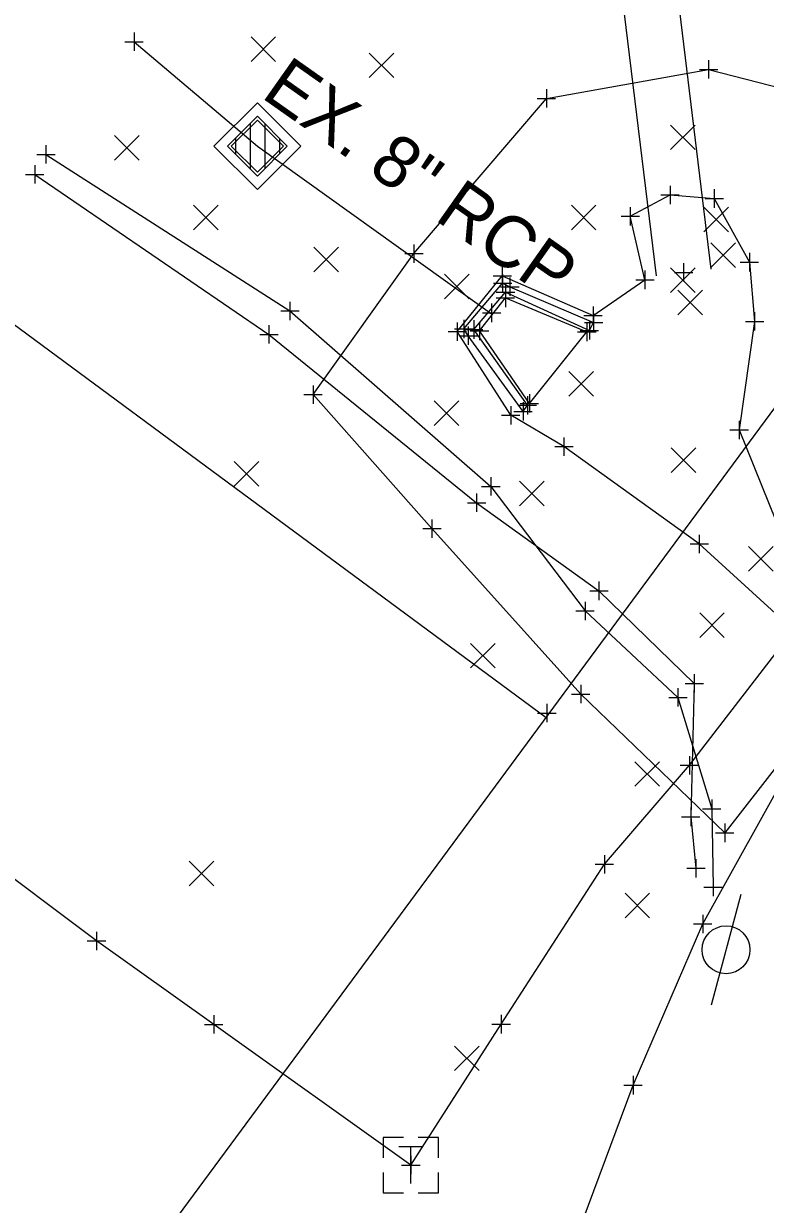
# Model space of a CAD drawing. Extents: x 1324089 to 1329959, y 459099 to 462017.
# Drawn here: x 1325717.7 to 1325758, y 460930.3 to 460994.4 of the extents above; entities that cross this region are included whole.
import ezdxf

# ---------------------------------------------------------------- set-up
doc = ezdxf.new("R2010")
doc.units = 0
for name, color, linetype in [('Default', 7, 'Continuous'), ('DR_X_Cells', 7, 'Continuous'), ('DR_X_Elev_Flow', 7, 'Continuous'), ('DR_X_Storm_Sewer', 7, 'Continuous'), ('DV_X_Property_Line', 7, 'Continuous'), ('GK_Drainage_Nodes', 7, 'Continuous'), ('PV_X_EOP', 7, 'Continuous'), ('RD_X_Wall', 7, 'Continuous'), ('RW_X_Fee_RW', 7, 'Continuous'), ('SV_X_Break_Lines', 7, 'Continuous'), ('SV_X_Random_Point', 7, 'Continuous'), ('SV_X_Shot_Marker', 7, 'Continuous'), ('UT_X_Electric', 7, 'Continuous'), ('UT_X_Telecom', 7, 'Continuous'), ('UT_X_Telecom_Cells', 7, 'Continuous'), ('UT_X_Unknown_Cells', 7, 'Continuous')]:
    doc.layers.add(name, color=color, linetype=linetype)

msp = doc.modelspace()

# ---------------------------------------------------------------- linework, layer by layer
at = {"layer": 'DR_X_Cells'}
for p, q in [((1325730.027, 460986.552), (1325730.027, 460989.039)), ((1325730.827, 460986.598), (1325730.827, 460988.992)), ((1325729.227, 460987.352), (1325729.227, 460988.239)), ((1325731.627, 460987.398), (1325731.627, 460988.192))]:
    msp.add_line(p, q, dxfattribs=at)
for points in [[(1325728.047, 460987.795), (1325730.404, 460990.152), (1325732.761, 460987.795), (1325730.404, 460985.438)], [(1325728.783, 460987.795), (1325730.404, 460989.416), (1325732.024, 460987.795), (1325730.404, 460986.175)], [(1325728.989, 460987.795), (1325730.404, 460989.21), (1325731.818, 460987.795), (1325730.404, 460986.381)]]:
    msp.add_lwpolyline(points, close=True, dxfattribs=at)
at = {"layer": 'DR_X_Elev_Flow'}
for p, q in [((1325723.706, 460993.967), (1325723.706, 460992.967)), ((1325723.206, 460993.467), (1325724.206, 460993.467)), ((1325723.706, 460993.467), (1325723.706, 460993.467)), ((1325753.054, 460980.942), (1325754.054, 460980.942)), ((1325753.554, 460981.442), (1325753.554, 460980.442)), ((1325753.554, 460980.942), (1325753.554, 460980.942))]:
    msp.add_line(p, q, dxfattribs=at)
at = {"layer": 'DR_X_Storm_Sewer'}
for p, q in [((1325747.138, 461045.572), (1325755.043, 460981.125)), ((1325744.161, 461045.207), (1325752.065, 460980.759)), ((1325744.161, 461045.207), (1325752.065, 460980.759)), ((1325723.706, 460993.467), (1325730.404, 460987.795)), ((1325730.404, 460987.795), (1325743.172, 460978.659))]:
    msp.add_line(p, q, dxfattribs=at)
at = {"layer": 'DV_X_Property_Line'}
msp.add_line((1325585.214, 461075.604), (1325746.083, 460956.772), dxfattribs=at)
at = {"layer": 'GK_Drainage_Nodes'}
for p, q in [((1325729.225, 460988.974), (1325729.225, 460988.974)), ((1325729.697, 460988.502), (1325729.697, 460988.502)), ((1325731.111, 460988.502), (1325731.111, 460988.502)), ((1325730.404, 460987.795), (1325730.404, 460987.795)), ((1325730.404, 460987.795), (1325730.404, 460987.795)), ((1325730.404, 460987.795), (1325730.404, 460987.795)), ((1325729.697, 460987.088), (1325729.697, 460987.088)), ((1325731.111, 460987.088), (1325731.111, 460987.088)), ((1325731.582, 460986.617), (1325731.582, 460986.617))]:
    msp.add_line(p, q, dxfattribs=at)
at = {"layer": 'PV_X_EOP'}
msp.add_lwpolyline([(1325745.179, 460973.829), (1325748.299, 460977.713)], dxfattribs=at)
at = {"layer": 'RD_X_Wall'}
for points in [[(1325744.833, 460973.4), (1325741.863, 460977.504), (1325741.618, 460977.871), (1325743.727, 460980.352), (1325744.118, 460980.163), (1325748.67, 460978.223)], [(1325744.833, 460973.4), (1325745.07, 460973.728), (1325742.154, 460977.841), (1325743.884, 460979.876), (1325748.441, 460977.795), (1325748.67, 460978.223)]]:
    msp.add_lwpolyline(points, dxfattribs=at)
at = {"layer": 'RW_X_Fee_RW'}
msp.add_line((1325448.762, 460554.274), (1326011.051, 461315.471), dxfattribs=at)
at = {"layer": 'SV_X_Break_Lines'}
for points in [[(1325755.792, 460950.517), (1325747.971, 460958.055), (1325739.888, 460967.035), (1325733.431, 460974.308), (1325738.909, 460981.966), (1325746.102, 460990.388), (1325754.917, 460991.961), (1325762.313, 460990.056), (1325767.82, 460985.73), (1325776.392, 460978.257)], [(1325745.179, 460973.829), (1325742.472, 460977.764), (1325743.876, 460979.559), (1325748.299, 460977.713)], [(1325602.569, 460725.503), (1325611.535, 460737.32), (1325631.624, 460762.971), (1325651.116, 460791.065), (1325670.213, 460817.468), (1325692.281, 460846.55), (1325713.18, 460875.417), (1325733.816, 460902.837), (1325743.825, 460918.052), (1325750.809, 460936.819), (1325754.596, 460945.574), (1325761.22, 460957.492), (1325755.792, 460950.517)]]:
    msp.add_lwpolyline(points, dxfattribs=at)
msp.add_lwpolyline([(1325761.22, 460957.492), (1325761.412, 460958.176), (1325758.753, 460962.25), (1325754.408, 460966.201), (1325747.053, 460971.488), (1325744.168, 460973.186), (1325741.264, 460977.729), (1325743.709, 460980.748), (1325748.637, 460978.595), (1325751.459, 460980.538), (1325750.657, 460983.988), (1325752.818, 460985.149), (1325755.224, 460984.954), (1325757.128, 460981.497), (1325757.411, 460978.28), (1325756.573, 460972.388), (1325758.586, 460967.416), (1325763.061, 460961.728), (1325765.859, 460959.222), (1325768.795, 460955.944), (1325766.752, 460951.889), (1325762.332, 460954.322), (1325762.039, 460955.973)], close=True, dxfattribs=at)
at = {"layer": 'SV_X_Random_Point'}
for p, q in [((1325730.064, 460992.393), (1325731.397, 460993.728)), ((1325730.064, 460993.728), (1325731.397, 460992.393)), ((1325736.486, 460991.515), (1325737.82, 460992.85)), ((1325736.486, 460992.85), (1325737.82, 460991.515)), ((1325752.852, 460987.606), (1325754.186, 460988.941)), ((1325752.852, 460988.941), (1325754.186, 460987.606)), ((1325722.649, 460987.032), (1325723.982, 460988.367)), ((1325722.649, 460988.367), (1325723.982, 460987.032)), ((1325726.941, 460983.252), (1325728.274, 460984.587)), ((1325726.941, 460984.587), (1325728.274, 460983.252)), ((1325747.459, 460983.256), (1325748.793, 460984.591)), ((1325747.459, 460984.591), (1325748.793, 460983.256)), ((1325754.658, 460983.146), (1325755.991, 460984.481)), ((1325754.658, 460984.481), (1325755.991, 460983.146)), ((1325733.469, 460980.978), (1325734.803, 460982.313)), ((1325733.469, 460982.313), (1325734.803, 460980.978)), ((1325755.037, 460981.214), (1325756.37, 460982.549)), ((1325755.037, 460982.549), (1325756.37, 460981.214)), ((1325740.567, 460979.511), (1325741.9, 460980.846)), ((1325740.567, 460980.846), (1325741.9, 460979.511)), ((1325752.85, 460979.857), (1325754.184, 460981.192)), ((1325752.85, 460981.192), (1325754.184, 460979.857)), ((1325753.249, 460978.637), (1325754.583, 460979.972)), ((1325753.249, 460979.972), (1325754.583, 460978.637)), ((1325747.322, 460974.222), (1325748.656, 460975.557)), ((1325747.322, 460975.557), (1325748.656, 460974.222)), ((1325740.006, 460972.639), (1325741.339, 460973.975)), ((1325740.006, 460973.975), (1325741.339, 460972.639)), ((1325752.884, 460970.082), (1325754.218, 460971.417)), ((1325752.884, 460971.417), (1325754.218, 460970.082)), ((1325729.152, 460969.341), (1325730.485, 460970.676)), ((1325729.152, 460970.676), (1325730.485, 460969.341)), ((1325744.645, 460968.27), (1325745.978, 460969.605)), ((1325744.645, 460969.605), (1325745.978, 460968.27)), ((1325757.085, 460964.722), (1325758.418, 460966.057)), ((1325757.085, 460966.057), (1325758.418, 460964.722)), ((1325754.434, 460961.118), (1325755.767, 460962.453)), ((1325754.434, 460962.453), (1325755.767, 460961.118)), ((1325741.989, 460959.468), (1325743.322, 460960.803)), ((1325741.989, 460960.803), (1325743.322, 460959.468)), ((1325750.912, 460953.044), (1325752.245, 460954.379)), ((1325750.912, 460954.379), (1325752.245, 460953.044)), ((1325726.699, 460947.647), (1325728.033, 460948.982)), ((1325726.699, 460948.982), (1325728.033, 460947.647)), ((1325750.374, 460945.911), (1325751.707, 460947.246)), ((1325750.374, 460947.246), (1325751.707, 460945.911)), ((1325741.115, 460937.609), (1325742.449, 460938.944)), ((1325741.115, 460938.944), (1325742.449, 460937.609))]:
    msp.add_line(p, q, dxfattribs=at)
at = {"layer": 'SV_X_Shot_Marker'}
for p, q in [((1325754.917, 460992.461), (1325754.917, 460991.461)), ((1325754.417, 460991.961), (1325755.417, 460991.961)), ((1325754.917, 460991.961), (1325754.917, 460991.961)), ((1325746.102, 460990.888), (1325746.102, 460989.888)), ((1325745.602, 460990.388), (1325746.602, 460990.388)), ((1325746.102, 460990.388), (1325746.102, 460990.388)), ((1325718.424, 460987.346), (1325719.424, 460987.346)), ((1325718.924, 460987.846), (1325718.924, 460986.846)), ((1325718.924, 460987.346), (1325718.924, 460987.346)), ((1325718.309, 460986.764), (1325718.309, 460985.764)), ((1325717.809, 460986.264), (1325718.809, 460986.264)), ((1325718.309, 460986.264), (1325718.309, 460986.264)), ((1325752.818, 460985.649), (1325752.818, 460984.649)), ((1325755.224, 460985.454), (1325755.224, 460984.454)), ((1325752.318, 460985.149), (1325753.318, 460985.149)), ((1325752.818, 460985.149), (1325752.818, 460985.149)), ((1325754.724, 460984.954), (1325755.724, 460984.954)), ((1325755.224, 460984.954), (1325755.224, 460984.954)), ((1325750.657, 460984.488), (1325750.657, 460983.488)), ((1325750.157, 460983.988), (1325751.157, 460983.988)), ((1325750.657, 460983.988), (1325750.657, 460983.988)), ((1325738.909, 460982.466), (1325738.909, 460981.466)), ((1325738.409, 460981.966), (1325739.409, 460981.966)), ((1325738.909, 460981.966), (1325738.909, 460981.966)), ((1325756.628, 460981.497), (1325757.628, 460981.497)), ((1325757.128, 460981.997), (1325757.128, 460980.997)), ((1325757.128, 460981.497), (1325757.128, 460981.497)), ((1325743.709, 460981.248), (1325743.709, 460980.248)), ((1325743.727, 460980.852), (1325743.727, 460979.852)), ((1325751.459, 460981.038), (1325751.459, 460980.038)), ((1325743.209, 460980.748), (1325744.209, 460980.748)), ((1325743.227, 460980.352), (1325744.227, 460980.352)), ((1325743.709, 460980.748), (1325743.709, 460980.748)), ((1325743.727, 460980.352), (1325743.727, 460980.352)), ((1325743.884, 460980.376), (1325743.884, 460979.376)), ((1325744.118, 460980.663), (1325744.118, 460979.663)), ((1325750.959, 460980.538), (1325751.959, 460980.538)), ((1325751.459, 460980.538), (1325751.459, 460980.538)), ((1325743.376, 460979.559), (1325744.376, 460979.559)), ((1325743.384, 460979.876), (1325744.384, 460979.876)), ((1325743.618, 460980.163), (1325744.618, 460980.163)), ((1325743.876, 460980.059), (1325743.876, 460979.059)), ((1325743.876, 460979.559), (1325743.876, 460979.559)), ((1325743.884, 460979.876), (1325743.884, 460979.876)), ((1325744.118, 460980.163), (1325744.118, 460980.163)), ((1325732.176, 460979.348), (1325732.176, 460978.348)), ((1325743.129, 460979.25), (1325743.129, 460978.25)), ((1325748.637, 460979.095), (1325748.637, 460978.095)), ((1325731.676, 460978.848), (1325732.676, 460978.848)), ((1325732.176, 460978.848), (1325732.176, 460978.848)), ((1325741.618, 460978.371), (1325741.618, 460977.371)), ((1325742.154, 460978.341), (1325742.154, 460977.341)), ((1325742.472, 460978.264), (1325742.472, 460977.264)), ((1325742.629, 460978.75), (1325743.629, 460978.75)), ((1325743.129, 460978.75), (1325743.129, 460978.75)), ((1325748.137, 460978.595), (1325749.137, 460978.595)), ((1325748.441, 460978.295), (1325748.441, 460977.295)), ((1325748.637, 460978.595), (1325748.637, 460978.595)), ((1325748.67, 460978.723), (1325748.67, 460977.723)), ((1325748.67, 460978.723), (1325748.67, 460977.723)), ((1325756.911, 460978.28), (1325757.911, 460978.28)), ((1325757.411, 460978.78), (1325757.411, 460977.78)), ((1325757.411, 460978.28), (1325757.411, 460978.28)), ((1325731.031, 460978.08), (1325731.031, 460977.08)), ((1325740.764, 460977.729), (1325741.764, 460977.729)), ((1325741.118, 460977.871), (1325742.118, 460977.871)), ((1325741.264, 460978.229), (1325741.264, 460977.229)), ((1325741.264, 460977.729), (1325741.264, 460977.729)), ((1325741.618, 460977.871), (1325741.618, 460977.871)), ((1325741.654, 460977.841), (1325742.654, 460977.841)), ((1325741.863, 460978.004), (1325741.863, 460977.004)), ((1325741.972, 460977.764), (1325742.972, 460977.764)), ((1325742.154, 460977.841), (1325742.154, 460977.841)), ((1325742.472, 460977.764), (1325742.472, 460977.764)), ((1325747.799, 460977.713), (1325748.799, 460977.713)), ((1325747.799, 460977.713), (1325748.799, 460977.713)), ((1325747.941, 460977.795), (1325748.941, 460977.795)), ((1325748.17, 460978.223), (1325749.17, 460978.223)), ((1325748.17, 460978.223), (1325749.17, 460978.223)), ((1325748.299, 460978.213), (1325748.299, 460977.213)), ((1325748.299, 460978.213), (1325748.299, 460977.213)), ((1325748.299, 460977.713), (1325748.299, 460977.713)), ((1325748.299, 460977.713), (1325748.299, 460977.713)), ((1325748.441, 460977.795), (1325748.441, 460977.795)), ((1325748.67, 460978.223), (1325748.67, 460978.223)), ((1325748.67, 460978.223), (1325748.67, 460978.223)), ((1325730.531, 460977.58), (1325731.531, 460977.58)), ((1325731.031, 460977.58), (1325731.031, 460977.58)), ((1325741.363, 460977.504), (1325742.363, 460977.504)), ((1325741.863, 460977.504), (1325741.863, 460977.504)), ((1325733.431, 460974.808), (1325733.431, 460973.808)), ((1325732.931, 460974.308), (1325733.931, 460974.308)), ((1325733.431, 460974.308), (1325733.431, 460974.308)), ((1325744.679, 460973.829), (1325745.679, 460973.829)), ((1325744.679, 460973.829), (1325745.679, 460973.829)), ((1325744.833, 460973.9), (1325744.833, 460972.9)), ((1325744.833, 460973.9), (1325744.833, 460972.9)), ((1325745.07, 460974.228), (1325745.07, 460973.228)), ((1325745.179, 460974.329), (1325745.179, 460973.329)), ((1325745.179, 460974.329), (1325745.179, 460973.329)), ((1325745.179, 460973.829), (1325745.179, 460973.829)), ((1325745.179, 460973.829), (1325745.179, 460973.829)), ((1325743.668, 460973.186), (1325744.668, 460973.186)), ((1325744.168, 460973.686), (1325744.168, 460972.686)), ((1325744.168, 460973.186), (1325744.168, 460973.186)), ((1325744.333, 460973.4), (1325745.333, 460973.4)), ((1325744.333, 460973.4), (1325745.333, 460973.4)), ((1325744.57, 460973.728), (1325745.57, 460973.728)), ((1325744.833, 460973.4), (1325744.833, 460973.4)), ((1325744.833, 460973.4), (1325744.833, 460973.4)), ((1325745.07, 460973.728), (1325745.07, 460973.728)), ((1325756.573, 460972.888), (1325756.573, 460971.888)), ((1325747.053, 460971.988), (1325747.053, 460970.988)), ((1325756.073, 460972.388), (1325757.073, 460972.388)), ((1325756.573, 460972.388), (1325756.573, 460972.388)), ((1325746.553, 460971.488), (1325747.553, 460971.488)), ((1325747.053, 460971.488), (1325747.053, 460971.488)), ((1325742.586, 460969.325), (1325743.586, 460969.325)), ((1325743.086, 460969.825), (1325743.086, 460968.825)), ((1325743.086, 460969.325), (1325743.086, 460969.325)), ((1325742.311, 460968.938), (1325742.311, 460967.938)), ((1325741.811, 460968.438), (1325742.811, 460968.438)), ((1325742.311, 460968.438), (1325742.311, 460968.438)), ((1325739.888, 460967.535), (1325739.888, 460966.535)), ((1325739.388, 460967.035), (1325740.388, 460967.035)), ((1325739.888, 460967.035), (1325739.888, 460967.035)), ((1325753.908, 460966.201), (1325754.908, 460966.201)), ((1325754.408, 460966.701), (1325754.408, 460965.701)), ((1325754.408, 460966.201), (1325754.408, 460966.201)), ((1325748.958, 460964.155), (1325748.958, 460963.155)), ((1325748.458, 460963.655), (1325749.458, 460963.655)), ((1325748.958, 460963.655), (1325748.958, 460963.655)), ((1325748.201, 460963.066), (1325748.201, 460962.066)), ((1325747.701, 460962.566), (1325748.701, 460962.566)), ((1325748.201, 460962.566), (1325748.201, 460962.566)), ((1325754.138, 460959.134), (1325754.138, 460958.134)), ((1325747.971, 460958.555), (1325747.971, 460957.555)), ((1325753.638, 460958.634), (1325754.638, 460958.634)), ((1325754.138, 460958.634), (1325754.138, 460958.634)), ((1325747.471, 460958.055), (1325748.471, 460958.055)), ((1325747.971, 460958.055), (1325747.971, 460958.055)), ((1325752.746, 460957.873), (1325753.746, 460957.873)), ((1325753.246, 460958.373), (1325753.246, 460957.373)), ((1325753.246, 460957.873), (1325753.246, 460957.873)), ((1325746.128, 460957.521), (1325746.128, 460956.521)), ((1325745.628, 460957.021), (1325746.628, 460957.021)), ((1325746.128, 460957.021), (1325746.128, 460957.021)), ((1325753.874, 460954.688), (1325753.874, 460953.688)), ((1325753.374, 460954.188), (1325754.374, 460954.188)), ((1325753.874, 460954.188), (1325753.874, 460954.188)), ((1325755.086, 460952.322), (1325755.086, 460951.322)), ((1325753.442, 460951.386), (1325754.442, 460951.386)), ((1325753.942, 460951.886), (1325753.942, 460950.886)), ((1325753.942, 460951.386), (1325753.942, 460951.386)), ((1325754.586, 460951.822), (1325755.586, 460951.822)), ((1325755.086, 460951.822), (1325755.086, 460951.822)), ((1325755.792, 460951.017), (1325755.792, 460950.017)), ((1325755.792, 460951.017), (1325755.792, 460950.017)), ((1325755.292, 460950.517), (1325756.292, 460950.517)), ((1325755.292, 460950.517), (1325756.292, 460950.517)), ((1325755.792, 460950.517), (1325755.792, 460950.517)), ((1325755.792, 460950.517), (1325755.792, 460950.517)), ((1325748.752, 460948.815), (1325749.752, 460948.815)), ((1325749.252, 460949.315), (1325749.252, 460948.315)), ((1325749.252, 460948.815), (1325749.252, 460948.815)), ((1325754.225, 460949.096), (1325754.225, 460948.096)), ((1325753.725, 460948.596), (1325754.725, 460948.596)), ((1325754.225, 460948.596), (1325754.225, 460948.596)), ((1325754.657, 460947.577), (1325755.657, 460947.577)), ((1325755.157, 460948.077), (1325755.157, 460947.077)), ((1325755.157, 460947.577), (1325755.157, 460947.577)), ((1325754.096, 460945.574), (1325755.096, 460945.574)), ((1325754.596, 460946.074), (1325754.596, 460945.074)), ((1325754.596, 460945.574), (1325754.596, 460945.574)), ((1325721.668, 460945.15), (1325721.668, 460944.15)), ((1325721.168, 460944.65), (1325722.168, 460944.65)), ((1325721.668, 460944.65), (1325721.668, 460944.65)), ((1325728.032, 460940.617), (1325728.032, 460939.617)), ((1325743.645, 460940.63), (1325743.645, 460939.63)), ((1325727.532, 460940.117), (1325728.532, 460940.117)), ((1325728.032, 460940.117), (1325728.032, 460940.117)), ((1325743.145, 460940.13), (1325744.145, 460940.13)), ((1325743.645, 460940.13), (1325743.645, 460940.13)), ((1325750.809, 460937.319), (1325750.809, 460936.319)), ((1325750.309, 460936.819), (1325751.309, 460936.819)), ((1325750.809, 460936.819), (1325750.809, 460936.819)), ((1325738.74, 460932.983), (1325738.74, 460931.983)), ((1325738.74, 460932.983), (1325738.74, 460931.983)), ((1325738.24, 460932.483), (1325739.24, 460932.483)), ((1325738.24, 460932.483), (1325739.24, 460932.483)), ((1325738.74, 460932.483), (1325738.74, 460932.483)), ((1325738.74, 460932.483), (1325738.74, 460932.483))]:
    msp.add_line(p, q, dxfattribs=at)
at = {"layer": 'UT_X_Electric'}
msp.add_lwpolyline([(1325718.924, 460987.346), (1325732.176, 460978.848), (1325743.086, 460969.325), (1325748.201, 460962.566), (1325753.246, 460957.873), (1325755.086, 460951.822), (1325755.157, 460947.577)], dxfattribs=at)
at = {"layer": 'UT_X_Telecom'}
for points in [[(1325738.74, 460932.483), (1325743.645, 460940.13), (1325749.252, 460948.815), (1325753.874, 460954.188), (1325760.392, 460962.64), (1325766.576, 460970.181), (1325777.411, 460984.097), (1325792.957, 461001.921)], [(1325718.309, 460986.264), (1325731.031, 460977.58), (1325742.311, 460968.438), (1325748.958, 460963.655), (1325754.138, 460958.634), (1325753.942, 460951.386), (1325754.225, 460948.596)], [(1325738.74, 460932.483), (1325728.032, 460940.117), (1325721.668, 460944.65), (1325715.046, 460949.611), (1325708.828, 460954.254), (1325701.947, 460959.574)]]:
    msp.add_lwpolyline(points, dxfattribs=at)
at = {"layer": 'UT_X_Telecom_Cells'}
for p, q in [((1325738.09, 460933.483), (1325739.39, 460933.483)), ((1325738.74, 460931.483), (1325738.74, 460933.483)), ((1325738.74, 460932.483), (1325738.74, 460932.483))]:
    msp.add_line(p, q, dxfattribs=at)
for points in [[(1325738.34, 460933.983), (1325737.24, 460933.983), (1325737.24, 460932.883)], [(1325740.24, 460932.883), (1325740.24, 460933.983), (1325739.14, 460933.983)], [(1325737.24, 460932.083), (1325737.24, 460930.983), (1325738.34, 460930.983)], [(1325739.14, 460930.983), (1325740.24, 460930.983), (1325740.24, 460932.083)]]:
    msp.add_lwpolyline(points, dxfattribs=at)
at = {"layer": 'UT_X_Unknown_Cells'}
msp.add_line((1325756.664, 460947.17), (1325755.057, 460941.17), dxfattribs=at)
msp.add_circle((1325755.86, 460944.17), 1.3, dxfattribs=at)

# ---------------------------------------------------------------- texts
at = {"layer": 'Default'}
msp.add_text('EX. 8" RCP', height=2.8, rotation=324.8242, dxfattribs=at).set_placement((1325730.543, 460990.483))

doc.saveas('drawing.dxf')
